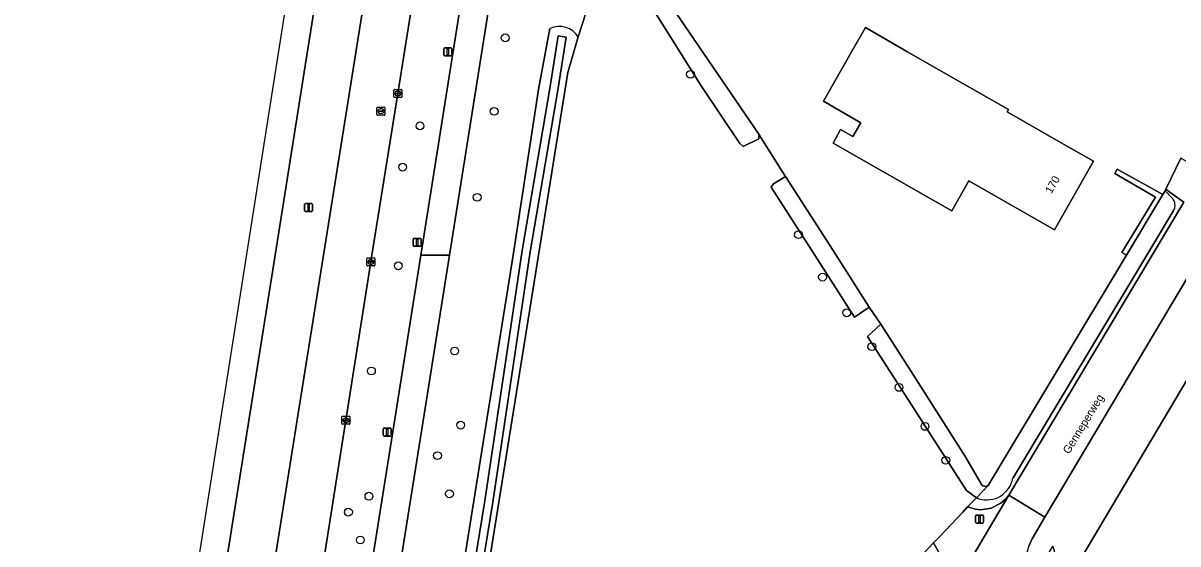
# Model space of a CAD drawing. Extents: x 160203 to 161530, y 379528 to 381797.
# Drawn here: x 160230.3 to 160374.5, y 379963.9 to 380029 of the extents above; entities that cross this region are included whole.
import ezdxf

# ---------------------------------------------------------------- set-up
doc = ezdxf.new("R2010")
doc.units = 0
for name, color, linetype in [('IMGEO_Berm_groen', 7, 'Continuous'), ('IMGEO_Boom', 7, 'Continuous'), ('IMGEO_Erf', 7, 'Continuous'), ('IMGEO_Fietspad_gesloten', 7, 'Continuous'), ('IMGEO_Grasland_agrarisch', 7, 'Continuous'), ('IMGEO_Groenvoorziening', 7, 'Continuous'), ('IMGEO_Haag', 7, 'Continuous'), ('IMGEO_Hek', 7, 'Continuous'), ('IMGEO_Kolk', 7, 'Continuous'), ('IMGEO_Lichtmast', 7, 'Continuous'), ('IMGEO_Loofbos', 7, 'Continuous'), ('IMGEO_Oever', 7, 'Continuous'), ('IMGEO_Openbare_ruimte_label', 7, 'Continuous'), ('IMGEO_Pand', 7, 'Continuous'), ('IMGEO_Pand_nummerreeks', 7, 'Continuous'), ('IMGEO_Rijbaan_lokaal_gesloten', 7, 'Continuous'), ('IMGEO_Rijbaan_lokaal_open', 7, 'Continuous'), ('IMGEO_Rijbaan_regionaal_gesloten', 7, 'Continuous'), ('IMGEO_Rioolput', 7, 'Continuous'), ('IMGEO_Waterloop', 7, 'Continuous')]:
    doc.layers.add(name, color=color, linetype=linetype)

msp = doc.modelspace()

# ---------------------------------------------------------------- linework, layer by layer
at = {"layer": 'IMGEO_Berm_groen'}
for points in [[(160290.49, 380180.23), (160283.58, 380137.11), (160271.43, 380060.8), (160267.03, 380033.12), (160261.76, 380000), (160240.13, 379864)], [(160246, 379863.01), (160264.67, 379980.23), (160267.81, 380000), (160272.93, 380032.15), (160277.33, 380059.83), (160289.51, 380136.18), (160296.4, 380179.3)], [(160352.43, 379969.02), (160353.08, 379969.61), (160353.43, 379970.05), (160371.33, 380000), (160375.27, 380006.61), (160373.71, 380007.73), (160373.06, 380008.26), (160372.96, 380008.04), (160373.8, 380007.18)], [(160373.96, 380005.5), (160370.65, 380000), (160353.95, 379972.21)], [(160375.89, 379997.42), (160357.91, 379967.3), (160356.34, 379964.6), (160355.94, 379963.68), (160355.63, 379962.74), (160355.41, 379961.77), (160355.27, 379960.79), (160355.22, 379959.8), (160355.26, 379958.81), (160355.39, 379957.82), (160355.43, 379957.61), (160358.93, 379963.68), (160360.33, 379958.58), (160382.33, 379995.65)], [(160349.37, 379969.72), (160348.7, 379969.01), (160348.28, 379968.57), (160349.28, 379968.28), (160349.93, 379968.22), (160351.24, 379968.42), (160352.43, 379969.02)]]:
    msp.add_lwpolyline(points, dxfattribs=at)
msp.add_lwpolyline([(160276.59, 379978.75), (160279.97, 380000), (160284.77, 380030.19), (160278.87, 380031.17), (160277.11, 380020.2), (160273.87, 380000), (160273.74, 379999.16), (160270.62, 379979.38), (160267.54, 379959.87), (160264.35, 379939.85), (160261.27, 379920.43), (160258.37, 379902.43), (160255, 379881.24), (160251.87, 379861.76), (160248.41, 379839.31), (160245.78, 379820.99), (160252.12, 379820.16), (160254.02, 379834.36), (160255.08, 379842.3), (160257.22, 379857.27)], close=True, dxfattribs=at)
for centre, radius, start, end in [((160372.9, 380006.25), 1.29, 324.7863, 45.9847), ((160350.67, 379972.78), 3.33, 246.9734, 343.0394), ((160350.74, 379972.77), 3.25, 342.8613, 350.2007)]:
    msp.add_arc(centre, radius, start, end, dxfattribs=at)
at = {"layer": 'IMGEO_Boom'}
for centre in [(160290.52, 380027.14), (160313.66, 380022.59), (160289.13, 380017.96), (160279.87, 380016.15), (160277.71, 380011), (160287.02, 380007.23), (160327.16, 380002.56), (160277.16, 379998.68), (160330.15, 379997.26), (160333.18, 379992.81), (160336.32, 379988.58), (160284.2, 379988.03), (160273.8, 379985.54), (160339.71, 379983.49), (160284.95, 379978.78), (160342.95, 379978.62), (160282.05, 379974.97), (160345.55, 379974.39), (160273.49, 379969.9), (160283.55, 379970.2), (160270.93, 379967.91), (160272.42, 379964.44)]:
    msp.add_circle(centre, 0.489, dxfattribs=at)
at = {"layer": 'IMGEO_Erf'}
msp.add_lwpolyline([(160303.16, 380043), (160322.21, 380015.12), (160322.67, 380014.38), (160325.08, 380010.54), (160325.52, 380009.84), (160331.84, 380000), (160335.99, 379993.53), (160337.45, 379991.38), (160340.63, 379986.39), (160347.92, 379974.93), (160350.09, 379971.23), (160350.52, 379971.11), (160350.83, 379971.26), (160368.12, 380000), (160367.56, 380000.32), (160371.74, 380007.24), (160366.65, 380010.21), (160366.97, 380010.76), (160372.68, 380007.58), (160372.96, 380008.04), (160373.06, 380008.26), (160374.9, 380012.13)], dxfattribs=at)
for points in [[(160348.42, 380009.29), (160346.29, 380005.56), (160343.62, 380007.08), (160331.47, 380014.01), (160332.42, 380015.68), (160333.95, 380014.81), (160334.94, 380016.55), (160330.26, 380019.22), (160333.9, 380025.59), (160335.52, 380028.43), (160340.67, 380025.43), (160345.85, 380022.48), (160353.37, 380018.19), (160353.21, 380017.9), (160359.68, 380014.22), (160364.02, 380011.74), (160359.14, 380003.18)], [(160407.99, 379995.8), (160400.24, 379995.97), (160382.33, 379995.65), (160360.33, 379958.58), (160368.22, 379945.15), (160400.15, 379946.25), (160408.91, 379946.67)]]:
    msp.add_lwpolyline(points, close=True, dxfattribs=at)
at = {"layer": 'IMGEO_Fietspad_gesloten'}
msp.add_lwpolyline([(160302, 380138.34), (160301.46, 380134.98), (160295.04, 380095.12), (160292.61, 380079.46), (160284.77, 380030.19), (160279.97, 380000), (160283.54, 380000), (160288.25, 380029.61), (160296.05, 380078.64), (160304.95, 380134.52), (160305.52, 380137.94)], close=True, dxfattribs=at)
msp.add_lwpolyline([(160256.53, 379826.14), (160258.63, 379841.98), (160260.67, 379856.52), (160280.08, 379978.27), (160283.54, 380000), (160279.97, 380000), (160276.59, 379978.75), (160257.22, 379857.27), (160255.08, 379842.3), (160254.02, 379834.36), (160252.12, 379820.16), (160251.72, 379817.19), (160250.59, 379808.35), (160247.8, 379786.96), (160246.21, 379773.5)], dxfattribs=at)
at = {"layer": 'IMGEO_Grasland_agrarisch'}
for points in [[(160343.37, 379963.38), (160344.03, 379964.08), (160344.8, 379964.89), (160347.68, 379967.93), (160348.28, 379968.57), (160348.7, 379969.01), (160349.37, 379969.72), (160348.14, 379970.62), (160340.15, 379983.05), (160335.78, 379989.85), (160337.45, 379991.38), (160335.99, 379993.53), (160334.14, 379992.28), (160329.19, 380000), (160323.75, 380008.48), (160324.03, 380008.91), (160325.52, 380009.84), (160325.08, 380010.54), (160322.67, 380014.38), (160322.21, 380015.12), (160322.18, 380014.54), (160320.25, 380013.57), (160319.82, 380013.95), (160315, 380021.17), (160302.71, 380040.76)], [(160300.6, 380030.21), (160299.63, 380027.26), (160298.32, 380022.82), (160294.66, 380000), (160269.1, 379840.82)]]:
    msp.add_lwpolyline(points, dxfattribs=at)
at = {"layer": 'IMGEO_Groenvoorziening'}
for points in [[(160303.16, 380043), (160302.53, 380043.92), (160302.2, 380043.41), (160301.36, 380042.91), (160302.71, 380040.76), (160315, 380021.17), (160319.82, 380013.95), (160320.25, 380013.57), (160322.18, 380014.54), (160322.21, 380015.12)], [(160368.12, 380000), (160372.68, 380007.58), (160366.97, 380010.76), (160366.65, 380010.21), (160371.74, 380007.24), (160367.56, 380000.32)], [(160353.43, 379970.05), (160353.08, 379969.61), (160352.43, 379969.02), (160351.24, 379968.42), (160349.93, 379968.22), (160349.28, 379968.28), (160348.28, 379968.57), (160347.68, 379967.93), (160344.8, 379964.89), (160344.03, 379964.08), (160344.58, 379963.06), (160344.85, 379962.42), (160345.12, 379961.53), (160345.38, 379959.7), (160345.26, 379957.86), (160345.05, 379956.96), (160344.76, 379956.08), (160343.99, 379954.59), (160345.72, 379957.12), (160346.32, 379958)]]:
    msp.add_lwpolyline(points, close=True, dxfattribs=at)
at = {"layer": 'IMGEO_Haag'}
msp.add_lwpolyline([(160368.12, 380000), (160372.68, 380007.58), (160366.97, 380010.76), (160366.65, 380010.21), (160371.74, 380007.24), (160367.56, 380000.32)], close=True, dxfattribs=at)
at = {"layer": 'IMGEO_Hek'}
for points in [[(160349.37, 379969.72), (160350.83, 379971.26)], [(160344.03, 379964.08), (160344.8, 379964.89), (160347.68, 379967.93), (160348.28, 379968.57)], [(160348.28, 379968.57), (160348.7, 379969.01), (160349.37, 379969.72)], [(160339.72, 379959.52), (160340.64, 379960.5), (160343.37, 379963.38), (160344.03, 379964.08)]]:
    msp.add_lwpolyline(points, dxfattribs=at)
at = {"layer": 'IMGEO_Kolk'}
for p, q in [((160276.61, 380019.77), (160276.61, 380020.63)), ((160276.69, 380020.7), (160277.54, 380020.7)), ((160277.1, 380020.48), (160277.13, 380020.48)), ((160277.61, 380020.63), (160277.61, 380019.77)), ((160277.54, 380019.7), (160276.69, 380019.7)), ((160276.87, 380020.19), (160276.87, 380020.21)), ((160276.91, 380020.24), (160277.31, 380020.24)), ((160277.31, 380020.16), (160276.91, 380020.16)), ((160277.12, 380019.92), (160277.1, 380019.92)), ((160277.36, 380020.21), (160277.36, 380020.19)), ((160273.24, 379998.74), (160273.24, 379999.59)), ((160273.31, 379999.66), (160274.17, 379999.66)), ((160273.5, 379999.16), (160273.5, 379999.17)), ((160273.54, 379999.21), (160273.94, 379999.21)), ((160273.94, 379999.12), (160273.54, 379999.12)), ((160273.75, 379998.88), (160273.72, 379998.88)), ((160273.73, 379999.44), (160273.75, 379999.44)), ((160273.98, 379999.17), (160273.98, 379999.16)), ((160274.24, 379999.59), (160274.24, 379998.74)), ((160274.17, 379998.66), (160273.31, 379998.66)), ((160270.12, 379978.95), (160270.12, 379979.8)), ((160270.19, 379979.88), (160271.05, 379979.88)), ((160271.05, 379978.88), (160270.19, 379978.88)), ((160270.38, 379979.37), (160270.38, 379979.38)), ((160270.42, 379979.42), (160270.82, 379979.42)), ((160270.82, 379979.33), (160270.42, 379979.33)), ((160270.63, 379979.1), (160270.6, 379979.1)), ((160270.61, 379979.66), (160270.63, 379979.66)), ((160270.86, 379979.38), (160270.86, 379979.37)), ((160271.12, 379979.8), (160271.12, 379978.95))]:
    msp.add_line(p, q, dxfattribs=at)
for points in [[(160276.61, 380019.77), (160276.61, 380020.63)], [(160276.69, 380020.7), (160277.54, 380020.7)], [(160277.61, 380020.63), (160277.61, 380019.77)], [(160277.54, 380019.7), (160276.69, 380019.7)], [(160273.24, 379998.74), (160273.24, 379999.59)], [(160273.31, 379999.66), (160274.17, 379999.66)], [(160274.24, 379999.59), (160274.24, 379998.74)], [(160274.17, 379998.66), (160273.31, 379998.66)], [(160270.12, 379978.95), (160270.12, 379979.8)], [(160270.19, 379979.88), (160271.05, 379979.88)], [(160271.05, 379978.88), (160270.19, 379978.88)], [(160271.12, 379979.8), (160271.12, 379978.95)]]:
    msp.add_lwpolyline(points, dxfattribs=at)
for centre, radius, start, end in [((160276.69, 380020.63), 0.0765, 91.552, 178.448), ((160276.69, 380020.63), 0.0765, 91.552, 178.448), ((160277.54, 380020.63), 0.0765, 1.552, 88.448), ((160277.54, 380020.63), 0.0765, 1.552, 88.448), ((160276.69, 380019.78), 0.0765, 181.552, 268.448), ((160276.69, 380019.78), 0.0765, 181.552, 268.448), ((160276.91, 380020.2), 0.0403, 85.8775, 175.7526), ((160276.91, 380020.19), 0.0366, 178.938, 274.7102), ((160277.32, 380020.21), 0.0386, 1.7309, 96.639), ((160277.31, 380020.2), 0.043, 264.8664, 352.4533), ((160277.54, 380019.78), 0.0765, 271.552, 358.448), ((160277.54, 380019.78), 0.0765, 271.552, 358.448), ((160273.32, 379999.59), 0.0765, 91.552, 178.448), ((160273.32, 379999.59), 0.0765, 91.552, 178.448), ((160273.54, 379999.17), 0.0403, 85.8775, 175.7526), ((160273.53, 379999.16), 0.0366, 178.938, 274.7102), ((160273.94, 379999.17), 0.0386, 1.7309, 96.639), ((160273.94, 379999.16), 0.043, 264.8664, 352.4533), ((160274.16, 379999.59), 0.0765, 1.552, 88.448), ((160274.16, 379999.59), 0.0765, 1.552, 88.448), ((160273.32, 379998.74), 0.0765, 181.552, 268.448), ((160273.32, 379998.74), 0.0765, 181.552, 268.448), ((160274.16, 379998.74), 0.0765, 271.552, 358.448), ((160274.16, 379998.74), 0.0765, 271.552, 358.448), ((160270.2, 379979.8), 0.0765, 91.552, 178.448), ((160270.2, 379979.8), 0.0765, 91.552, 178.448), ((160270.2, 379978.95), 0.0765, 181.552, 268.448), ((160270.2, 379978.95), 0.0765, 181.552, 268.448), ((160270.42, 379979.38), 0.0403, 85.8775, 175.7526), ((160270.41, 379979.37), 0.0366, 178.938, 274.7102), ((160270.82, 379979.38), 0.0386, 1.7309, 96.639), ((160270.82, 379979.38), 0.043, 264.8664, 352.4533), ((160271.04, 379979.8), 0.0765, 1.552, 88.448), ((160271.04, 379979.8), 0.0765, 1.552, 88.448), ((160271.04, 379978.95), 0.0765, 271.552, 358.448), ((160271.04, 379978.95), 0.0765, 271.552, 358.448)]:
    msp.add_arc(centre, radius, start, end, dxfattribs=at)
for centre, major_axis, ratio, start_param, end_param in [((160277.1, 380020.2), (-0.387, 0.002), 0.722429, 4.712389, 7.853982), ((160277.12, 380020.2), (-0.39, 0.002), 0.717154, 1.570796, 4.712389), ((160273.73, 379999.16), (-0.387, 0.002), 0.722429, 4.712389, 7.853982), ((160273.75, 379999.16), (-0.39, 0.002), 0.717154, 1.570796, 4.712389), ((160270.61, 379979.38), (-0.387, 0.002), 0.722429, 4.712389, 7.853982), ((160270.63, 379979.38), (-0.39, 0.002), 0.717154, 1.570796, 4.712389)]:
    msp.add_ellipse(centre, major_axis=major_axis, ratio=ratio, start_param=start_param, end_param=end_param, dxfattribs=at)
at = {"layer": 'IMGEO_Lichtmast'}
for p, q in [((160282.86, 380024.99), (160282.86, 380025.79)), ((160282.86, 380025.79), (160282.86, 380024.99)), ((160282.96, 380025.89), (160283.75, 380025.89)), ((160283.75, 380025.89), (160282.96, 380025.89)), ((160283.75, 380024.89), (160282.96, 380024.89)), ((160282.96, 380024.89), (160283.75, 380024.89)), ((160283.85, 380025.79), (160283.85, 380024.99)), ((160283.85, 380024.99), (160283.85, 380025.79)), ((160265.46, 380005.55), (160265.46, 380006.35)), ((160265.46, 380006.35), (160265.46, 380005.55)), ((160265.56, 380006.45), (160266.34, 380006.45)), ((160266.34, 380006.45), (160265.56, 380006.45)), ((160266.44, 380006.35), (160266.44, 380005.55)), ((160266.44, 380005.55), (160266.44, 380006.35)), ((160266.34, 380005.45), (160265.56, 380005.45)), ((160265.56, 380005.45), (160266.34, 380005.45)), ((160279.03, 380001.21), (160279.03, 380002)), ((160279.03, 380002), (160279.03, 380001.21)), ((160279.13, 380002.1), (160279.92, 380002.1)), ((160279.92, 380002.1), (160279.13, 380002.1)), ((160280.02, 380002), (160280.02, 380001.21)), ((160280.02, 380001.21), (160280.02, 380002)), ((160279.92, 380001.11), (160279.13, 380001.11)), ((160279.13, 380001.11), (160279.92, 380001.11)), ((160275.28, 379977.51), (160275.28, 379978.31)), ((160275.28, 379978.31), (160275.28, 379977.51)), ((160275.38, 379978.41), (160276.17, 379978.41)), ((160276.17, 379978.41), (160275.38, 379978.41)), ((160276.17, 379977.41), (160275.38, 379977.41)), ((160275.38, 379977.41), (160276.17, 379977.41)), ((160276.27, 379978.31), (160276.27, 379977.51)), ((160276.27, 379977.51), (160276.27, 379978.31)), ((160349.27, 379966.65), (160349.27, 379967.45)), ((160349.27, 379967.45), (160349.27, 379966.65)), ((160349.37, 379967.55), (160350.16, 379967.55)), ((160350.16, 379967.55), (160349.37, 379967.55)), ((160350.26, 379967.45), (160350.26, 379966.65)), ((160350.26, 379966.65), (160350.26, 379967.45)), ((160350.16, 379966.55), (160349.37, 379966.55)), ((160349.37, 379966.55), (160350.16, 379966.55))]:
    msp.add_line(p, q, dxfattribs=at)
for points in [[(160283.28, 380025.76), (160283.43, 380025.76), (160283.43, 380025.01), (160283.28, 380025.01), (160283.28, 380025.76)], [(160265.88, 380006.32), (160266.03, 380006.32), (160266.03, 380005.57), (160265.88, 380005.57), (160265.88, 380006.32)], [(160279.45, 380001.98), (160279.6, 380001.98), (160279.6, 380001.23), (160279.45, 380001.23), (160279.45, 380001.98)], [(160275.7, 379978.29), (160275.85, 379978.29), (160275.85, 379977.54), (160275.7, 379977.54), (160275.7, 379978.29)], [(160349.69, 379967.43), (160349.84, 379967.43), (160349.84, 379966.68), (160349.69, 379966.68), (160349.69, 379967.43)]]:
    msp.add_lwpolyline(points, dxfattribs=at)
for centre, start, end in [((160282.96, 380025.79), 90, 180), ((160282.96, 380025.79), 90, 180), ((160282.96, 380024.99), 180, 270), ((160282.96, 380024.99), 180, 270), ((160283.75, 380025.79), 0, 90), ((160283.75, 380025.79), 360, 90), ((160283.75, 380024.99), 270, 0), ((160283.75, 380024.99), 270, 0), ((160265.56, 380006.35), 90, 180), ((160265.56, 380006.35), 90, 180), ((160266.34, 380006.35), 0, 90), ((160266.34, 380006.35), 360, 90), ((160265.56, 380005.55), 180, 270), ((160265.56, 380005.55), 180, 270), ((160266.34, 380005.55), 270, 0), ((160266.34, 380005.55), 270, 0), ((160279.13, 380002), 90, 180), ((160279.13, 380002), 90, 180), ((160279.92, 380002), 0, 90), ((160279.92, 380002), 360, 90), ((160279.13, 380001.21), 180, 270), ((160279.13, 380001.21), 180, 270), ((160279.92, 380001.21), 270, 0), ((160279.92, 380001.21), 270, 0), ((160275.38, 379978.31), 90, 180), ((160275.38, 379978.31), 90, 180), ((160275.38, 379977.51), 180, 270), ((160275.38, 379977.51), 180, 270), ((160276.17, 379978.31), 0, 90), ((160276.17, 379978.31), 360, 90), ((160276.17, 379977.51), 270, 0), ((160276.17, 379977.51), 270, 0), ((160349.37, 379967.45), 90, 180), ((160349.37, 379967.45), 90, 180), ((160350.16, 379967.45), 0, 90), ((160350.16, 379967.45), 360, 90), ((160349.37, 379966.65), 180, 270), ((160349.37, 379966.65), 180, 270), ((160350.16, 379966.65), 270, 0), ((160350.16, 379966.65), 270, 0)]:
    msp.add_arc(centre, 0.1, start, end, dxfattribs=at)
at = {"layer": 'IMGEO_Loofbos'}
for points in [[(160298.95, 380048.76), (160307.5, 380101.17), (160329.39, 380237.95), (160320.36, 380230.75), (160305.52, 380137.94), (160304.95, 380134.52), (160296.05, 380078.64), (160288.25, 380029.61), (160283.54, 380000), (160280.08, 379978.27), (160260.67, 379856.52), (160258.63, 379841.98), (160256.53, 379826.14)], [(160299.63, 380027.26), (160300.6, 380030.21), (160301.39, 380034.16), (160302.71, 380040.76), (160301.36, 380042.91), (160300.24, 380042.89)], [(160343.99, 379954.59), (160344.76, 379956.08), (160345.05, 379956.96), (160345.26, 379957.86), (160345.38, 379959.7), (160345.12, 379961.53), (160344.85, 379962.42), (160344.58, 379963.06), (160344.03, 379964.08), (160343.37, 379963.38), (160340.64, 379960.5), (160339.72, 379959.52), (160309.99, 379909.32), (160298.15, 379889.57), (160271.43, 379843.62), (160269.94, 379840.82), (160269.1, 379840.82), (160268.4, 379836.24), (160266.62, 379836.23), (160265.32, 379836.48), (160291.49, 380000), (160294.67, 380020.68), (160296.11, 380028.32)]]:
    msp.add_lwpolyline(points, dxfattribs=at)
msp.add_arc((160297.28, 380025.82), 2.75, 31.3711, 115.066, dxfattribs=at)
at = {"layer": 'IMGEO_Oever'}
for points in [[(160296.11, 380028.32), (160294.67, 380020.68), (160291.49, 380000), (160265.32, 379836.48), (160266.62, 379836.23), (160268.4, 379836.24), (160269.1, 379840.82), (160294.66, 380000)], [(160294.66, 380000), (160298.32, 380022.82), (160299.63, 380027.26)]]:
    msp.add_lwpolyline(points, dxfattribs=at)
msp.add_lwpolyline([(160267.74, 379837.35), (160266.75, 379837.51), (160272.07, 379871.14), (160275.08, 379890.17), (160279.66, 379918.25), (160282.98, 379938.72), (160287.95, 379969.32), (160292.64, 380000.58), (160296.1, 380020.8), (160297.14, 380027.39), (160298.14, 380027.24), (160297.1, 380020.63), (160293.64, 380000.42), (160288.95, 379969.16), (160283.98, 379938.56), (160280.66, 379918.09), (160276.08, 379890.01), (160273.07, 379870.98)], close=True, dxfattribs=at)
msp.add_arc((160297.28, 380025.82), 2.75, 31.3711, 115.066, dxfattribs=at)
at = {"layer": 'IMGEO_Pand'}
msp.add_lwpolyline([(160353.21, 380017.9), (160353.37, 380018.19), (160345.85, 380022.48), (160340.67, 380025.43), (160335.52, 380028.43), (160333.9, 380025.59), (160330.26, 380019.22), (160334.94, 380016.55), (160333.95, 380014.81), (160332.42, 380015.68), (160331.47, 380014.01), (160343.62, 380007.08), (160346.29, 380005.56), (160348.42, 380009.29), (160359.14, 380003.18), (160364.02, 380011.74), (160359.68, 380014.22)], close=True, dxfattribs=at)
at = {"layer": 'IMGEO_Rijbaan_lokaal_gesloten'}
msp.add_lwpolyline([(160355.94, 379963.68), (160356.34, 379964.6), (160357.91, 379967.3), (160353.43, 379970.05), (160346.32, 379958)], dxfattribs=at)
at = {"layer": 'IMGEO_Rijbaan_lokaal_open'}
msp.add_lwpolyline([(160456.74, 380133.28), (160462.03, 380142.26), (160457.51, 380144.89), (160452.03, 380135.62), (160388.75, 380029.17), (160377.87, 380010.95), (160375.99, 380011.51), (160374.9, 380012.13), (160373.06, 380008.26), (160373.71, 380007.73), (160375.27, 380006.61), (160371.33, 380000), (160353.43, 379970.05), (160357.91, 379967.3), (160375.89, 379997.42)], dxfattribs=at)
at = {"layer": 'IMGEO_Rijbaan_regionaal_gesloten'}
msp.add_lwpolyline([(160230.29, 379823.03), (160233.89, 379822.55), (160236.49, 379840.86), (160240.13, 379864), (160261.76, 380000), (160267.03, 380033.12), (160263.48, 380033.71)], close=True, dxfattribs=at)
msp.add_lwpolyline([(160267.54, 379959.87), (160270.62, 379979.38), (160273.74, 379999.16), (160273.87, 380000), (160277.11, 380020.2), (160278.87, 380031.17), (160272.93, 380032.15), (160267.81, 380000), (160264.67, 379980.23), (160246, 379863.01)], dxfattribs=at)
at = {"layer": 'IMGEO_Rioolput'}
for p, q in [((160274.48, 380017.56), (160274.48, 380018.42)), ((160274.56, 380018.49), (160275.41, 380018.49)), ((160274.74, 380017.98), (160274.74, 380018)), ((160275.18, 380017.95), (160274.78, 380017.95)), ((160274.79, 380018.03), (160275.18, 380018.03)), ((160274.97, 380018.27), (160275, 380018.27)), ((160274.99, 380017.71), (160274.97, 380017.71)), ((160275.23, 380018), (160275.23, 380017.98)), ((160275.49, 380018.42), (160275.49, 380017.56)), ((160275.41, 380017.49), (160274.56, 380017.49))]:
    msp.add_line(p, q, dxfattribs=at)
for points in [[(160274.48, 380017.56), (160274.48, 380018.42)], [(160274.56, 380018.49), (160275.41, 380018.49)], [(160275.49, 380018.42), (160275.49, 380017.56)], [(160275.41, 380017.49), (160274.56, 380017.49)]]:
    msp.add_lwpolyline(points, dxfattribs=at)
for centre, radius, start, end in [((160274.56, 380018.41), 0.0765, 91.552, 178.448), ((160274.56, 380018.41), 0.0765, 91.552, 178.448), ((160274.56, 380017.56), 0.0765, 181.552, 268.448), ((160274.56, 380017.56), 0.0765, 181.552, 268.448), ((160274.78, 380017.99), 0.0403, 85.8775, 175.7526), ((160274.78, 380017.98), 0.0366, 178.938, 274.7102), ((160275.19, 380017.99), 0.0386, 1.7309, 96.639), ((160275.18, 380017.99), 0.043, 264.8664, 352.4533), ((160275.41, 380018.41), 0.0765, 1.552, 88.448), ((160275.41, 380018.41), 0.0765, 1.552, 88.448), ((160275.41, 380017.56), 0.0765, 271.552, 358.448), ((160275.41, 380017.56), 0.0765, 271.552, 358.448)]:
    msp.add_arc(centre, radius, start, end, dxfattribs=at)
for centre, major_axis, ratio, start_param, end_param in [((160274.97, 380017.99), (-0.387, 0.002), 0.722429, 4.712389, 7.853982), ((160275, 380017.99), (-0.39, 0.002), 0.717154, 1.570796, 4.712389)]:
    msp.add_ellipse(centre, major_axis=major_axis, ratio=ratio, start_param=start_param, end_param=end_param, dxfattribs=at)
at = {"layer": 'IMGEO_Waterloop'}
for points in [[(160297.1, 380020.63), (160298.14, 380027.24), (160297.14, 380027.39), (160296.1, 380020.8), (160292.64, 380000.58), (160287.95, 379969.32), (160282.98, 379938.72), (160279.66, 379918.25), (160275.08, 379890.17), (160272.07, 379871.14), (160266.75, 379837.51), (160267.74, 379837.35), (160273.07, 379870.98), (160276.08, 379890.01), (160280.66, 379918.09), (160283.98, 379938.56), (160288.95, 379969.16), (160293.64, 380000.42)], [(160331.84, 380000), (160325.52, 380009.84), (160324.03, 380008.91), (160323.75, 380008.48), (160329.19, 380000), (160334.14, 379992.28), (160335.99, 379993.53)]]:
    msp.add_lwpolyline(points, close=True, dxfattribs=at)
for points in [[(160373.8, 380007.18), (160372.96, 380008.04), (160372.68, 380007.58), (160368.12, 380000), (160350.83, 379971.26), (160350.52, 379971.11), (160350.09, 379971.23), (160347.92, 379974.93), (160340.63, 379986.39), (160337.45, 379991.38), (160335.78, 379989.85), (160340.15, 379983.05), (160348.14, 379970.62), (160349.37, 379969.72)], [(160353.95, 379972.21), (160370.65, 380000), (160373.96, 380005.5)]]:
    msp.add_lwpolyline(points, dxfattribs=at)
for centre, radius, start, end in [((160372.9, 380006.25), 1.29, 324.7863, 45.9847), ((160350.67, 379972.78), 3.33, 246.9734, 343.0394), ((160350.74, 379972.77), 3.25, 342.8613, 350.2007)]:
    msp.add_arc(centre, radius, start, end, dxfattribs=at)

# ---------------------------------------------------------------- texts
at = {"layer": 'IMGEO_Openbare_ruimte_label'}
msp.add_text('Genneperweg', height=1, rotation=58.4563, dxfattribs=at).set_placement((160360.95, 379975.09))
at = {"layer": 'IMGEO_Pand_nummerreeks'}
msp.add_text('170', height=1, rotation=60.3153, dxfattribs=at).set_placement((160358.75, 380007.6))

doc.saveas('drawing.dxf')
